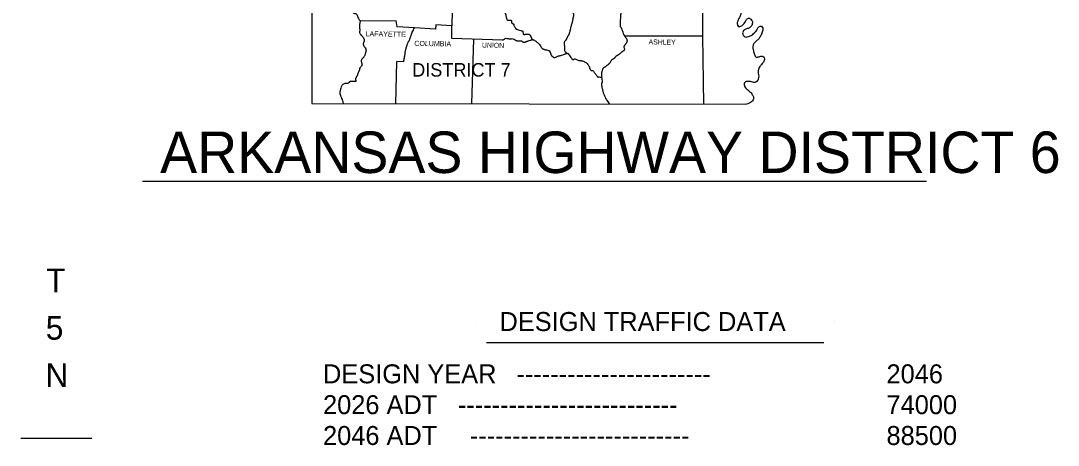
# Model space of a CAD drawing. Extents: x 1373878 to 1386598, y 1168333 to 1170533.
# Drawn here: x 1376117 to 1376992, y 1169459 to 1169817 of the extents above; entities that cross this region are included whole.
import ezdxf

# ---------------------------------------------------------------- set-up
doc = ezdxf.new("R2010")
doc.units = 0
for name, color, linetype in [('1', 7, 'Continuous'), ('Default', 7, 'Continuous'), ('R_Dimension', 7, 'Continuous'), ('R_Draft', 7, 'Continuous')]:
    doc.layers.add(name, color=color, linetype=linetype)

msp = doc.modelspace()

# ---------------------------------------------------------------- linework, layer by layer
at = {"layer": '1'}
for points in [[(1376481.89, 1169862.81), (1376480.59, 1169812.41), (1376467.09, 1169813.31), (1376466.99, 1169809.61), (1376449.2, 1169810.66)], [(1376362.59, 1169827.81), (1376362.79, 1169746.92), (1376729.29, 1169746.32)], [(1376440.19, 1169782.42), (1376433.99, 1169782.02), (1376433.31, 1169746.8)]]:
    msp.add_lwpolyline(points, dxfattribs=at)
for points in [[(1376744.59, 1169884.11), (1376743.59, 1169881.81), (1376742.49, 1169877.81), (1376742.79, 1169874.41), (1376744.29, 1169871.51), (1376746.69, 1169869.91), (1376749.29, 1169867.61), (1376749.09, 1169864.11), (1376747.59, 1169862.81), (1376744.09, 1169863.71), (1376741.39, 1169864.91), (1376739.09, 1169864.21), (1376735.99, 1169862.71), (1376733.69, 1169862.41), (1376733.79, 1169857.61), (1376736.89, 1169854.21), (1376739.59, 1169854.21), (1376742.69, 1169853.81), (1376743.79, 1169850.21), (1376741.99, 1169847.21), (1376738.99, 1169845.71), (1376735.19, 1169847.51), (1376732.49, 1169849.41), (1376729.79, 1169851.21), (1376726.39, 1169852.11), (1376724.49, 1169851.71), (1376723.59, 1169847.51), (1376725.19, 1169843.71), (1376727.79, 1169841.11), (1376730.19, 1169837.71), (1376729.79, 1169835.21), (1376727.99, 1169834.51), (1376724.79, 1169833.81), (1376722.89, 1169832.81), (1376722.39, 1169832.01), (1376723.39, 1169828.61), (1376724.29, 1169824.91), (1376724.29, 1169822.11), (1376723.19, 1169819.51), (1376721.49, 1169815.51), (1376721.69, 1169812.91), (1376722.89, 1169811.71), (1376724.39, 1169812.11), (1376726.39, 1169813.51), (1376727.69, 1169815.11), (1376728.79, 1169817.11), (1376730.89, 1169818.81), (1376733.49, 1169817.31), (1376734.09, 1169814.21), (1376732.59, 1169811.51), (1376730.49, 1169810.31), (1376727.89, 1169809.31), (1376725.99, 1169807.11), (1376726.49, 1169804.51), (1376727.99, 1169803.11), (1376731.69, 1169803.81), (1376734.19, 1169804.91), (1376735.59, 1169806.31), (1376737.29, 1169808.01), (1376738.19, 1169809.71), (1376739.49, 1169811.51), (1376741.79, 1169812.01), (1376742.89, 1169810.51), (1376742.49, 1169807.11), (1376741.09, 1169803.91), (1376739.19, 1169801.21), (1376737.09, 1169799.31), (1376734.49, 1169795.21), (1376734.99, 1169791.41), (1376735.99, 1169788.31), (1376737.39, 1169785.91), (1376739.79, 1169786.41), (1376742.49, 1169786.71), (1376744.09, 1169785.41), (1376743.89, 1169782.62), (1376741.89, 1169779.92), (1376739.99, 1169777.32), (1376738.99, 1169773.72), (1376739.39, 1169771.22), (1376739.39, 1169768.92), (1376738.59, 1169766.42), (1376737.19, 1169765.02), (1376733.49, 1169765.12), (1376729.59, 1169765.52), (1376727.49, 1169764.32), (1376727.89, 1169760.92), (1376730.19, 1169758.42), (1376731.79, 1169757.12), (1376734.09, 1169754.32), (1376735.09, 1169752.02), (1376734.79, 1169750.02), (1376733.39, 1169748.32), (1376729.29, 1169746.32)], [(1376623.19, 1169823.31), (1376622.89, 1169820.21), (1376622.79, 1169817.31), (1376622.59, 1169814.51), (1376622.54, 1169813.46), (1376622.54, 1169812.94), (1376622.59, 1169812.41), (1376622.79, 1169811.81), (1376623.14, 1169811.25), (1376623.51, 1169810.7), (1376623.79, 1169810.11), (1376624.49, 1169807.91), (1376625.19, 1169806.01), (1376626.59, 1169803.51), (1376626.9, 1169803.03), (1376627.24, 1169802.57), (1376627.58, 1169802.1), (1376627.89, 1169801.61), (1376628.4, 1169800.27), (1376628.45, 1169799.57), (1376628.29, 1169798.91), (1376627.49, 1169797.51), (1376627.13, 1169796.98), (1376626.74, 1169796.46), (1376626.35, 1169795.94), (1376625.99, 1169795.41), (1376625.83, 1169794.5), (1376626.04, 1169793.46), (1376626.21, 1169792.44), (1376625.89, 1169791.61), (1376625.69, 1169791.43), (1376625.47, 1169791.28), (1376625, 1169791), (1376624.53, 1169790.72), (1376624.09, 1169790.41), (1376622.96, 1169789.4), (1376622.39, 1169788.89), (1376621.79, 1169788.41), (1376620.49, 1169787.51), (1376619.09, 1169786.61), (1376618.68, 1169786.26), (1376618.32, 1169785.84), (1376617.97, 1169785.41), (1376617.59, 1169785.01), (1376617.06, 1169784.62), (1376616.48, 1169784.29), (1376615.9, 1169783.94), (1376615.39, 1169783.52), (1376614.95, 1169782.93), (1376614.58, 1169782.28), (1376614.21, 1169781.63), (1376613.79, 1169781.02), (1376613.38, 1169780.51), (1376612.95, 1169780.01), (1376611.99, 1169779.12), (1376610.49, 1169778.12), (1376609.97, 1169777.8), (1376609.44, 1169777.49), (1376608.65, 1169777), (1376608.39, 1169776.82), (1376608.03, 1169776.41), (1376607.8, 1169775.91), (1376607.49, 1169774.82), (1376607.23, 1169773.89), (1376606.99, 1169772.97), (1376606.83, 1169772.05), (1376606.79, 1169771.12), (1376606.92, 1169769.76), (1376607.09, 1169768.42), (1376607.49, 1169766.02), (1376607.45, 1169765.27), (1376607.24, 1169764.52), (1376607.04, 1169763.77), (1376606.99, 1169763.02), (1376607.49, 1169759.72), (1376607.99, 1169757.12), (1376608.79, 1169754.82), (1376609.89, 1169752.22), (1376610.55, 1169750.99), (1376611.29, 1169749.82), (1376612.55, 1169748.11), (1376613.93, 1169746.5)], [(1376440.19, 1169782.42), (1376440.69, 1169785.61), (1376440.81, 1169786.24), (1376440.94, 1169786.87), (1376441.07, 1169787.49), (1376441.19, 1169788.11), (1376441.28, 1169788.71), (1376441.34, 1169789.31), (1376441.41, 1169789.92), (1376441.49, 1169790.51), (1376442.09, 1169793.21), (1376442.99, 1169796.11), (1376443.79, 1169798.51), (1376443.9, 1169798.74), (1376444.03, 1169798.96), (1376444.34, 1169799.37), (1376444.65, 1169799.77), (1376444.79, 1169799.99), (1376444.89, 1169800.21), (1376445.07, 1169800.71), (1376445.24, 1169801.21), (1376445.41, 1169801.72), (1376445.59, 1169802.21), (1376446.49, 1169804.61), (1376446.71, 1169805.24), (1376446.91, 1169805.88), (1376447.13, 1169806.51), (1376447.39, 1169807.11), (1376449.2, 1169810.66)]]:
    msp.add_spline(points, degree=3, dxfattribs=at)
at = {"layer": 'Default'}
for points in [[(1376691.99, 1169863.61), (1376691.99, 1169803.81), (1376692.79, 1169746.38)], [(1376433.79, 1169816.71), (1376403.49, 1169816.41)], [(1376449.2, 1169810.66), (1376434.49, 1169811.51), (1376433.79, 1169816.71)], [(1376523.49, 1169800.21), (1376480.79, 1169801.81), (1376480.59, 1169812.41)], [(1376499, 1169801.13), (1376497.41, 1169746.7)], [(1376626.34, 1169803.91), (1376691.99, 1169803.91)]]:
    msp.add_lwpolyline(points, dxfattribs=at)
for points in [[(1376548.16, 1169866.93), (1376548.09, 1169863.82), (1376548.02, 1169862.26), (1376547.97, 1169861.49), (1376547.89, 1169860.71), (1376547.59, 1169859.15), (1376547.19, 1169857.61), (1376546.93, 1169856.19), (1376546.76, 1169855.49), (1376546.64, 1169855.15), (1376546.57, 1169854.98), (1376546.49, 1169854.81), (1376546.19, 1169854.35), (1376545.81, 1169853.96), (1376544.99, 1169853.21), (1376544.19, 1169852.42), (1376543.39, 1169851.61), (1376541.89, 1169849.81), (1376541.55, 1169849.28), (1376541.25, 1169848.71), (1376540.94, 1169848.15), (1376540.59, 1169847.61), (1376539.29, 1169846.21), (1376537.59, 1169844.81), (1376535.89, 1169843.81), (1376533.99, 1169842.91), (1376533.48, 1169842.75), (1376532.95, 1169842.65), (1376532.42, 1169842.56), (1376531.89, 1169842.41), (1376531.06, 1169841.99), (1376530.7, 1169841.69), (1376530.54, 1169841.51), (1376530.39, 1169841.31), (1376530.13, 1169840.73), (1376530.04, 1169840.11), (1376530.29, 1169838.91), (1376530.7, 1169838.06), (1376531.15, 1169837.22), (1376531.59, 1169836.38), (1376531.99, 1169835.51), (1376532.59, 1169833.91), (1376532.73, 1169833.45), (1376532.81, 1169832.97), (1376532.84, 1169832.49), (1376532.79, 1169832.01), (1376532.09, 1169830.91), (1376530.49, 1169830.01), (1376528.59, 1169828.91), (1376526.89, 1169827.91), (1376526.49, 1169827.59), (1376526.16, 1169827.18), (1376525.9, 1169826.72), (1376525.69, 1169826.21), (1376525.42, 1169825.06), (1376525.49, 1169823.91), (1376525.68, 1169823.24), (1376525.89, 1169822.56), (1376526.11, 1169821.89), (1376526.29, 1169821.21), (1376526.44, 1169820.42), (1376526.59, 1169819.61), (1376526.98, 1169818.2), (1376527.33, 1169817.58), (1376527.58, 1169817.32), (1376527.73, 1169817.21), (1376527.89, 1169817.11), (1376528.14, 1169817.06), (1376528.39, 1169817.1), (1376528.64, 1169817.17), (1376528.89, 1169817.21), (1376529.12, 1169817.23), (1376529.34, 1169817.26), (1376529.8, 1169817.33), (1376530.25, 1169817.31), (1376530.47, 1169817.24), (1376530.58, 1169817.19), (1376530.69, 1169817.11), (1376530.84, 1169816.88), (1376530.89, 1169816.61), (1376530.99, 1169816.11), (1376531.39, 1169814.81), (1376531.69, 1169814.48), (1376532.14, 1169814.26), (1376532.59, 1169814.04), (1376532.89, 1169813.71), (1376532.96, 1169813.47), (1376533, 1169813.22), (1376533.03, 1169812.96), (1376533.09, 1169812.71), (1376533.47, 1169811.74), (1376533.99, 1169810.81), (1376534.31, 1169810.41), (1376534.66, 1169810.05), (1376535.49, 1169809.51), (1376536.59, 1169809.11), (1376538.89, 1169808.41), (1376540.09, 1169808.11), (1376540.26, 1169808.03), (1376540.58, 1169807.55), (1376540.73, 1169806.58), (1376540.89, 1169805.66), (1376541.08, 1169805.35), (1376541.39, 1169805.21), (1376542.19, 1169805.22), (1376542.99, 1169805.31), (1376544.19, 1169805.51), (1376545.2, 1169805.47), (1376545.7, 1169805.3), (1376545.95, 1169805.17), (1376546.19, 1169805.01), (1376546.73, 1169804.45), (1376547.09, 1169803.81), (1376547.33, 1169803.32), (1376547.54, 1169802.82), (1376547.75, 1169802.31), (1376547.99, 1169801.81), (1376548.52, 1169801.05), (1376548.8, 1169800.75)], [(1376581.19, 1169852.41), (1376581.27, 1169850.86), (1376581.36, 1169849.31), (1376581.59, 1169846.21), (1376581.77, 1169845.45), (1376582.08, 1169844.71), (1376582.37, 1169843.97), (1376582.46, 1169843.6), (1376582.49, 1169843.21), (1376582.45, 1169842.42), (1376582.35, 1169841.62), (1376582.26, 1169840.82), (1376582.19, 1169840.01), (1376582.09, 1169836.91), (1376582.09, 1169834.11), (1376582.09, 1169831.41), (1376582.09, 1169828.61), (1376582.29, 1169826.61), (1376582.44, 1169825.88), (1376582.63, 1169825.16), (1376582.82, 1169824.44), (1376582.99, 1169823.71), (1376583.24, 1169822.36), (1376583.3, 1169821.69), (1376583.29, 1169821.01), (1376583.19, 1169820.36), (1376583.02, 1169819.71), (1376582.84, 1169819.07), (1376582.69, 1169818.41), (1376582.62, 1169817.82), (1376582.57, 1169817.21), (1376582.5, 1169816.61), (1376582.39, 1169816.01), (1376582.21, 1169815.41), (1376582, 1169814.81), (1376581.78, 1169814.22), (1376581.59, 1169813.61), (1376580.89, 1169810.91), (1376580.09, 1169807.41), (1376579.78, 1169806.25), (1376579.6, 1169805.68), (1376579.39, 1169805.11), (1376579.09, 1169804.49), (1376578.72, 1169803.9), (1376578.34, 1169803.31), (1376577.99, 1169802.71), (1376577.75, 1169802.17), (1376577.54, 1169801.62), (1376577.33, 1169801.06), (1376577.09, 1169800.51), (1376576.78, 1169800.14), (1376576.37, 1169799.84), (1376575.96, 1169799.53), (1376575.8, 1169799.34), (1376575.69, 1169799.11), (1376575.47, 1169797.92), (1376575.49, 1169796.71), (1376575.56, 1169796.16), (1376575.65, 1169795.61), (1376575.74, 1169795.06), (1376575.79, 1169794.51), (1376575.77, 1169794.02), (1376575.7, 1169793.52), (1376575.62, 1169793.01), (1376575.59, 1169792.51), (1376575.77, 1169791.55), (1376576.29, 1169790.61), (1376576.63, 1169790.21), (1376576.99, 1169789.82), (1376577.72, 1169789.32)], [(1376362.59, 1169827.81), (1376366.09, 1169829.31), (1376367.59, 1169828.81), (1376368.89, 1169827.51), (1376370.39, 1169827.51), (1376371.19, 1169828.71), (1376372.69, 1169828.81), (1376373.89, 1169828.71), (1376375.19, 1169829.51), (1376376.29, 1169830.01), (1376377.79, 1169830.51), (1376378.89, 1169830.91), (1376379.89, 1169832.01), (1376381.69, 1169832.91), (1376383.79, 1169833.61), (1376384.39, 1169834.61), (1376385.39, 1169835.01), (1376387.39, 1169834.91), (1376388.69, 1169835.51), (1376389.79, 1169835.01), (1376390.79, 1169834.31), (1376390.99, 1169831.71), (1376391.79, 1169830.31), (1376392.99, 1169827.81), (1376394.69, 1169826.51), (1376396.29, 1169825.21), (1376396.89, 1169824.41), (1376398.59, 1169822.91), (1376400.09, 1169822.41), (1376400.79, 1169821.31), (1376401.89, 1169818.71), (1376403.49, 1169816.41)], [(1376403.49, 1169816.41), (1376403.15, 1169815.13), (1376403.01, 1169814.31), (1376402.89, 1169813.51), (1376402.79, 1169811.21), (1376402.87, 1169810.53), (1376403.03, 1169809.85), (1376403.19, 1169809.18), (1376403.29, 1169808.51), (1376403.22, 1169808.19), (1376403.03, 1169807.86), (1376402.85, 1169807.54), (1376402.79, 1169807.21), (1376402.89, 1169806.73), (1376403.05, 1169806.26), (1376403.59, 1169805.31), (1376403.96, 1169804.89), (1376404.35, 1169804.53), (1376404.74, 1169804.19), (1376405.09, 1169803.81), (1376405.67, 1169803.05), (1376406.19, 1169802.21), (1376406.46, 1169801.64), (1376406.66, 1169801.06), (1376406.8, 1169800.49), (1376406.89, 1169799.91), (1376406.78, 1169799.26), (1376406.44, 1169798.61), (1376406.1, 1169797.96), (1376405.99, 1169797.31), (1376406.12, 1169796.64), (1376406.34, 1169795.96), (1376406.99, 1169794.61), (1376407.21, 1169794.34), (1376407.45, 1169794.12), (1376407.69, 1169793.89), (1376407.89, 1169793.61), (1376408.39, 1169792.01), (1376408.3, 1169791.24), (1376408.14, 1169790.46), (1376407.69, 1169788.91), (1376406.79, 1169786.61), (1376406.59, 1169786.29), (1376406.35, 1169786), (1376405.83, 1169785.45), (1376405.29, 1169784.9), (1376404.79, 1169784.32), (1376404.19, 1169783.22), (1376404.49, 1169781.72), (1376404.64, 1169781.11), (1376404.8, 1169780.51), (1376404.93, 1169779.91), (1376404.97, 1169779.61), (1376404.99, 1169779.46), (1376404.99, 1169779.32), (1376404.81, 1169778.95), (1376404.64, 1169778.78), (1376404.49, 1169778.62), (1376403.84, 1169777.77), (1376403.19, 1169776.92), (1376403.01, 1169776.48), (1376402.95, 1169775.98), (1376402.91, 1169775.48), (1376402.79, 1169775.02), (1376402.58, 1169774.61), (1376402.34, 1169774.22), (1376402.1, 1169773.82), (1376401.89, 1169773.42), (1376401.63, 1169772.7), (1376401.39, 1169771.97), (1376401.15, 1169771.23), (1376400.89, 1169770.52), (1376400.6, 1169769.9), (1376400.26, 1169769.3), (1376399.91, 1169768.71), (1376399.59, 1169768.12), (1376399.53, 1169767.36), (1376399.69, 1169766.47), (1376399.75, 1169765.72), (1376399.65, 1169765.5), (1376399.39, 1169765.42), (1376397.39, 1169765.42), (1376395.09, 1169765.42), (1376394.52, 1169765.21), (1376394.03, 1169764.74), (1376393.55, 1169764.24), (1376392.99, 1169763.92), (1376392.53, 1169763.86), (1376392.05, 1169763.86), (1376391.57, 1169763.87), (1376391.09, 1169763.82), (1376389.91, 1169763.5), (1376388.79, 1169762.92), (1376388.31, 1169762.51), (1376387.92, 1169762.06), (1376387.39, 1169761.02), (1376386.89, 1169758.92), (1376386.74, 1169758.42), (1376386.57, 1169757.92), (1376386.29, 1169756.92), (1376386.24, 1169756.07), (1376386.37, 1169755.21), (1376386.6, 1169754.35), (1376386.89, 1169753.52), (1376387.79, 1169751.12), (1376388.49, 1169749.22), (1376389.39, 1169746.87)], [(1376523.49, 1169800.21), (1376525.09, 1169801.31), (1376526.59, 1169801.91), (1376527.34, 1169801.78), (1376527.72, 1169801.69), (1376528.09, 1169801.61), (1376529.69, 1169801.41), (1376530.04, 1169801.43), (1376530.39, 1169801.5), (1376530.74, 1169801.58), (1376531.09, 1169801.61), (1376532.89, 1169801.31), (1376533.29, 1169801.11), (1376533.66, 1169800.87), (1376534.02, 1169800.63), (1376534.39, 1169800.41), (1376535.22, 1169799.96), (1376536.09, 1169799.71), (1376537.79, 1169799.71), (1376539.29, 1169799.71), (1376539.65, 1169799.59), (1376539.95, 1169799.3), (1376540.25, 1169799), (1376540.59, 1169798.81), (1376541.18, 1169798.73), (1376541.8, 1169798.71), (1376542.41, 1169798.77), (1376542.99, 1169798.91), (1376543.49, 1169799.11), (1376543.99, 1169799.32), (1376544.49, 1169799.53), (1376544.99, 1169799.71), (1376546.99, 1169800.31), (1376547.67, 1169800.52), (1376548.36, 1169800.69), (1376549.04, 1169800.76), (1376549.38, 1169800.72), (1376549.69, 1169800.61), (1376550.94, 1169799.84), (1376552.09, 1169798.91), (1376552.95, 1169798.23), (1376553.79, 1169797.51), (1376555.19, 1169795.91), (1376555.47, 1169795.48), (1376555.69, 1169795.02), (1376555.92, 1169794.56), (1376556.19, 1169794.11), (1376557.29, 1169793.11), (1376557.73, 1169792.89), (1376558.18, 1169792.7), (1376559.09, 1169792.41), (1376560.49, 1169792.11), (1376562.19, 1169791.61), (1376562.68, 1169791.48), (1376562.9, 1169791.38), (1376563.09, 1169791.21), (1376563.38, 1169790.77), (1376563.56, 1169790.29), (1376563.71, 1169789.8), (1376563.89, 1169789.31), (1376564.03, 1169788.99), (1376564.15, 1169788.66), (1376564.38, 1169788), (1376564.69, 1169787.35), (1376564.91, 1169787.03), (1376565.04, 1169786.87), (1376565.19, 1169786.71), (1376565.8, 1169786.22), (1376566.43, 1169785.89), (1376567.06, 1169785.75), (1376567.69, 1169785.81), (1376568.47, 1169786.08), (1376569.24, 1169786.41), (1376570.01, 1169786.74), (1376570.79, 1169787.01), (1376573.29, 1169787.71), (1376575.09, 1169788.31), (1376576.19, 1169788.71), (1376576.44, 1169788.76), (1376576.69, 1169788.77), (1376576.95, 1169788.77), (1376577.19, 1169788.81), (1376577.21, 1169788.83), (1376577.18, 1169788.85), (1376577.05, 1169788.91), (1376576.91, 1169788.97), (1376576.88, 1169788.99), (1376576.89, 1169789.01), (1376577.18, 1169789.15), (1376577.49, 1169789.27), (1376578.09, 1169789.31), (1376578.38, 1169789.2), (1376578.68, 1169789.02), (1376579.19, 1169788.51), (1376579.38, 1169788.24), (1376579.55, 1169787.96), (1376579.71, 1169787.68), (1376579.89, 1169787.41), (1376581.09, 1169785.81), (1376581.62, 1169785.11), (1376581.89, 1169784.76), (1376582.19, 1169784.42), (1376582.44, 1169784.21), (1376582.72, 1169784.07), (1376583.01, 1169783.97), (1376583.29, 1169783.92), (1376583.57, 1169784), (1376583.84, 1169784.24), (1376584.11, 1169784.46), (1376584.39, 1169784.52), (1376585.89, 1169784.02), (1376587.19, 1169783.52), (1376588.69, 1169783.12), (1376589.02, 1169783.07), (1376589.34, 1169783.06), (1376589.67, 1169783.05), (1376589.99, 1169783.02), (1376591.69, 1169782.62), (1376592.99, 1169781.92), (1376594.19, 1169781.22), (1376595.39, 1169779.92), (1376596.59, 1169777.92), (1376596.72, 1169777.53), (1376596.8, 1169777.12), (1376596.87, 1169776.71), (1376596.99, 1169776.32), (1376597.59, 1169775.42), (1376597.97, 1169775.05), (1376598.39, 1169774.72), (1376598.71, 1169774.66), (1376599.08, 1169774.75), (1376599.43, 1169774.82), (1376599.69, 1169774.72), (1376600.18, 1169774.07), (1376600.66, 1169773.42), (1376601.59, 1169772.12), (1376602.29, 1169771.12), (1376602.94, 1169770.15), (1376603.32, 1169769.71), (1376603.54, 1169769.5), (1376603.79, 1169769.32), (1376604.06, 1169769.23), (1376604.34, 1169769.26), (1376604.62, 1169769.31), (1376604.89, 1169769.32), (1376607.03, 1169768.91)]]:
    msp.add_spline(points, degree=3, dxfattribs=at)
at = {"layer": 'R_Dimension'}
msp.add_line((1376117.21, 1169464.83), (1376177.21, 1169464.82), dxfattribs=at)
at = {"layer": 'R_Draft'}
for p, q in [((1376219.85, 1169681.4), (1376881.07, 1169681.4)), ((1376501.09, 1169563.06), (1376501.09, 1169563.06)), ((1376803.31, 1169563.06), (1376803.31, 1169563.06)), ((1376509.98, 1169545.28), (1376794.42, 1169545.28))]:
    msp.add_line(p, q, dxfattribs=at)

# ---------------------------------------------------------------- texts
at = {"layer": 'Default'}
for s, height, rotation, p in [('LAFAYETTE', 4.299, 359.18389, (1376407.99, 1169803.61)), ('COLUMBIA', 4.299, 359.2125, (1376449.09, 1169795.51)), ('ASHLEY', 4.2, 359.23612, (1376646.59, 1169796.81)), ('UNION', 4.2, 358.9584, (1376506.09, 1169794.11))]:
    msp.add_text(s, height=height, rotation=rotation, dxfattribs=at).set_placement(p)
msp.add_text('DISTRICT 7', height=11.4, dxfattribs=at).set_placement((1376447.29, 1169769.62))
at = {"layer": 'R_Draft'}
for s, height, p in [('ARKANSAS HIGHWAY DISTRICT 6', 35, (1376234.75, 1169688.3)), ('T', 20, (1376138.63, 1169587.76)), ('5', 20, (1376138.26, 1169547.76)), ('DESIGN TRAFFIC DATA', 16, (1376520.91, 1169555.06)), ('N', 20, (1376138.07, 1169507.77)), ('DESIGN YEAR', 16, (1376372.1, 1169510.95)), ('2046', 16, (1376847.24, 1169510.95)), ('-----------------------', 16, (1376535.18, 1169510.95)), ('2026 ADT', 16, (1376372.1, 1169484.95)), ('74000', 16, (1376847.24, 1169484.95)), (' --------------------------', 16, (1376479.87, 1169484.95)), ('2046 ADT', 16, (1376372.1, 1169458.95)), ('88500', 16, (1376847.24, 1169458.95)), ('--------------------------', 16, (1376495.87, 1169458.95))]:
    msp.add_text(s, height=height, dxfattribs=at).set_placement(p)

doc.saveas('drawing.dxf')
